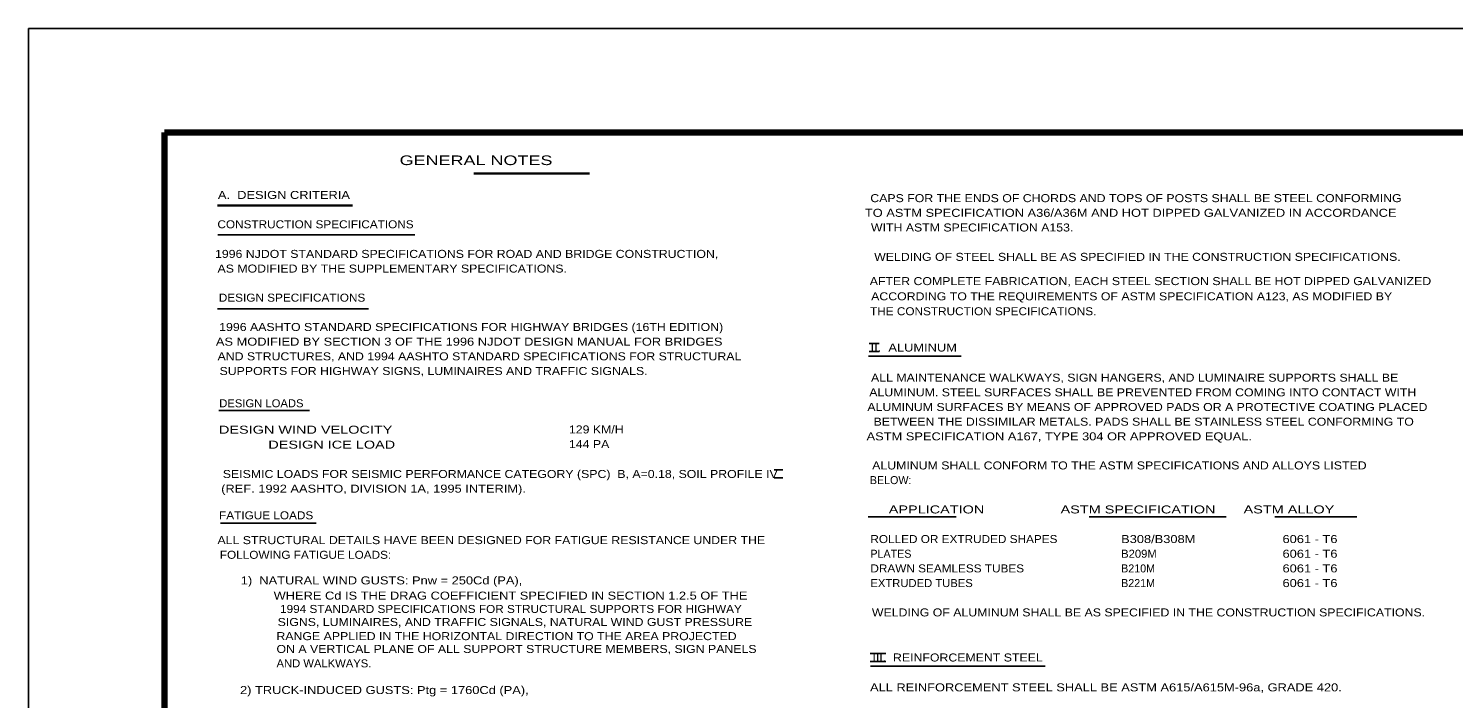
# Model space of a CAD drawing. Extents: x 312601.858 to 312602.699, y 144420.109 to 144420.704.
# Drawn here: x 312601.858 to 312602.392, y 144420.452 to 144420.704 of the extents above; entities that cross this region are included whole.
import ezdxf
from ezdxf.enums import TextEntityAlignment as Align

# ---------------------------------------------------------------- set-up
doc = ezdxf.new("R2010")
doc.units = 0
doc.header["$LTSCALE"] = 0.0012
for name, color, linetype, lineweight in [('1', 7, 'Continuous', 25), ('2', 7, 'Continuous', 25), ('39', 7, 'Continuous', 25)]:
    doc.layers.add(name, color=color, linetype=linetype, lineweight=lineweight)

msp = doc.modelspace()

# ---------------------------------------------------------------- linework, layer by layer
at = {"layer": '1', "lineweight": 35}
for p, q in [((312602.0247, 144420.6492), (312602.0681, 144420.6492)), ((312601.9286, 144420.6371), (312601.9793, 144420.6371))]:
    msp.add_line(p, q, dxfattribs=at)
at = {"layer": '1'}
for p, q in [((312601.9288, 144420.6262), (312602.0026, 144420.6262)), ((312601.9287, 144420.5984), (312601.9853, 144420.5984)), ((312602.173, 144420.5854), (312602.1767, 144420.5854)), ((312602.1727, 144420.5807), (312602.2074, 144420.5807)), ((312602.173, 144420.5824), (312602.1767, 144420.5824)), ((312601.9291, 144420.5603), (312601.9631, 144420.5603)), ((312602.1373, 144420.538), (312602.1406, 144420.538)), ((312602.1373, 144420.535), (312602.1406, 144420.535)), ((312602.1726, 144420.5204), (312602.2056, 144420.5204)), ((312602.2554, 144420.5204), (312602.3068, 144420.5204)), ((312602.325, 144420.5204), (312602.3557, 144420.5204)), ((312602.1733, 144420.4692), (312602.1792, 144420.4692)), ((312602.1733, 144420.4662), (312602.1792, 144420.4662)), ((312602.1734, 144420.4645), (312602.2389, 144420.4645))]:
    msp.add_line(p, q, dxfattribs=at)
at = {"layer": '2'}
msp.add_line((312601.9298, 144420.5181), (312601.9657, 144420.5181), dxfattribs=at)
at = {"layer": '39'}
for p, q in [((312601.8578, 144420.1095), (312601.8578, 144420.7035)), ((312601.8578, 144420.7035), (312602.6988, 144420.7035))]:
    msp.add_line(p, q, dxfattribs=at)
at = {"layer": '39', "lineweight": 158}
for p, q in [((312601.9088, 144420.1247), (312601.9088, 144420.6645)), ((312601.9088, 144420.6645), (312602.6838, 144420.6645))]:
    msp.add_line(p, q, dxfattribs=at)

# ---------------------------------------------------------------- texts
at = {"layer": '1'}
for s, width, p in [('129 KM/H', 1.15, (312602.0604, 144420.5517)), ('144 PA', 1.15, (312602.0604, 144420.5462)), ('ROLLED OR EXTRUDED SHAPES', 1.1, (312602.1734, 144420.5106)), ('B308/B308M', 1.2, (312602.2674, 144420.5106)), ('6061 - T6', 1.2, (312602.3279, 144420.5106)), ('B209M', 1.05, (312602.2674, 144420.5051)), ('6061 - T6', 1.2, (312602.3279, 144420.5051)), ('DRAWN SEAMLESS TUBES', 1.1, (312602.1734, 144420.4996)), ('6061 - T6', 1.2, (312602.3279, 144420.4996)), ('EXTRUDED TUBES', 1.05, (312602.1734, 144420.4941)), ('6061 - T6', 1.2, (312602.3279, 144420.4941))]:
    msp.add_text(s, height=0.003, dxfattribs=dict(at, width=width)).set_placement(p)
for s, p in [('PLATES', (312602.1734, 144420.5051)), ('B210M', (312602.2674, 144420.4996)), ('B221M', (312602.2674, 144420.4941))]:
    msp.add_text(s, height=0.003, dxfattribs=at).set_placement(p)
at = {"layer": '2'}
for s, height, width, p in [('                         GENERAL NOTES', 0.0036, 1.4, (312602.00215, 144420.6523)), ('A.  DESIGN CRITERIA', 0.003, 1.2, (312601.95355, 144420.6396)), ('CAPS FOR THE ENDS OF CHORDS AND TOPS OF POSTS SHALL BE STEEL CONFORMING ', 0.003, 1.15, (312602.2736, 144420.6384)), ('TO ASTM SPECIFICATION A36/A36M AND HOT DIPPED GALVANIZED IN ACCORDANCE ', 0.003, 1.2, (312602.27165, 144420.6329)), ('CONSTRUCTION SPECIFICATIONS', 0.003, 1.1, (312601.9654, 144420.6286)), ('WITH ASTM SPECIFICATION A153.', 0.003, 1.15, (312602.21155, 144420.6274)), ('1996 NJDOT STANDARD SPECIFICATIONS FOR ROAD AND BRIDGE CONSTRUCTION,', 0.003, 1.15, (312602.02205, 144420.6175)), ('WELDING OF STEEL SHALL BE AS SPECIFIED IN THE CONSTRUCTION SPECIFICATIONS. ', 0.003, 1.15, (312602.27415, 144420.6164)), ('AS MODIFIED BY THE SUPPLEMENTARY SPECIFICATIONS.', 0.003, 1.15, (312601.99415, 144420.612)), ('AFTER COMPLETE FABRICATION, EACH STEEL SECTION SHALL BE HOT DIPPED GALVANIZED', 0.003, 1.15, (312602.2784, 144420.6073)), ('DESIGN SPECIFICATIONS', 0.003, 1.1, (312601.9566, 144420.6011)), ('ACCORDING TO THE REQUIREMENTS OF ASTM SPECIFICATION A123, AS MODIFIED BY', 0.003, 1.15, (312602.27135, 144420.6016)), ('THE CONSTRUCTION SPECIFICATIONS.', 0.003, 1.1, (312602.2157, 144420.596)), ('1996 AASHTO STANDARD SPECIFICATIONS FOR HIGHWAY BRIDGES (16TH EDITION)', 0.003, 1.15, (312602.02375, 144420.5901)), ('AS MODIFIED BY SECTION 3 OF THE 1996 NJDOT DESIGN MANUAL FOR BRIDGES', 0.003, 1.2, (312602.023, 144420.5846)), ('II.  ALUMINUM', 0.003, 1.2, (312602.18965, 144420.5824)), ('AND STRUCTURES, AND 1994 AASHTO STANDARD SPECIFICATIONS FOR STRUCTURAL', 0.003, 1.15, (312602.02685, 144420.5791)), ('SUPPORTS FOR HIGHWAY SIGNS, LUMINAIRES AND TRAFFIC SIGNALS.', 0.003, 1.15, (312602.00965, 144420.5736)), ('ALL MAINTENANCE WALKWAYS, SIGN HANGERS, AND LUMINAIRE SUPPORTS SHALL BE  ', 0.003, 1.15, (312602.27375, 144420.5711)), ('ALUMINUM. STEEL SURFACES SHALL BE PREVENTED FROM COMING INTO CONTACT WITH ', 0.003, 1.15, (312602.27615, 144420.5656)), ('DESIGN LOADS', 0.003, 1.05, (312601.9451, 144420.5615)), ('ALUMINUM SURFACES BY MEANS OF APPROVED PADS OR A PROTECTIVE COATING PLACED', 0.003, 1.15, (312602.27725, 144420.5601)), ('BETWEEN THE DISSIMILAR METALS. PADS SHALL BE STAINLESS STEEL CONFORMING TO ', 0.003, 1.15, (312602.2765, 144420.5546)), ('ASTM SPECIFICATION A167, TYPE 304 OR APPROVED EQUAL.', 0.003, 1.2, (312602.2442, 144420.5491)), ('DESIGN ICE LOAD                                  ', 0.003, 1.35, (312601.99705, 144420.546)), ('ALUMINUM SHALL CONFORM TO THE ASTM SPECIFICATIONS AND ALLOYS LISTED', 0.003, 1.15, (312602.26675, 144420.5382)), ('SEISMIC LOADS FOR SEISMIC PERFORMANCE CATEGORY (SPC)  B, A=0.18, SOIL PROFILE IV', 0.003, 1.15, (312602.03465, 144420.535)), ('(REF. 1992 AASHTO, DIVISION 1A, 1995 INTERIM).', 0.003, 1.2, (312601.98715, 144420.5295)), ('FATIGUE LOADS', 0.003, 1.1, (312601.9469, 144420.5195)), ('APPLICATION                   ASTM SPECIFICATION       ASTM ALLOY', 0.003, 1.35, (312602.2638, 144420.5217)), ('APPLICATION                   ASTM SPECIFICATION       ASTM ALLOY', 0.003, 1.35, (312602.2638, 144420.5217)), ('ALL STRUCTURAL DETAILS HAVE BEEN DESIGNED FOR FATIGUE RESISTANCE UNDER THE', 0.003, 1.15, (312602.0313, 144420.5102)), ('FOLLOWING FATIGUE LOADS:', 0.003, 1.1, (312601.96165, 144420.5047)), ('1)  NATURAL WIND GUSTS: Pnw = 250Cd (PA),', 0.003, 1.2, (312601.99015, 144420.4951)), ('WHERE Cd IS THE DRAG COEFFICIENT SPECIFIED IN SECTION 1.2.5 OF THE', 0.003, 1.2, (312602.0385, 144420.4894)), ('1994 STANDARD SPECIFICATIONS FOR STRUCTURAL SUPPORTS FOR HIGHWAY', 0.003, 1.1, (312602.03865, 144420.4844)), ('SIGNS, LUMINAIRES, AND TRAFFIC SIGNALS, NATURAL WIND GUST PRESSURE', 0.003, 1.15, (312602.04015, 144420.4795)), ('WELDING OF ALUMINUM SHALL BE AS SPECIFIED IN THE CONSTRUCTION SPECIFICATIONS.', 0.003, 1.15, (312602.27765, 144420.4831)), ('RANGE APPLIED IN THE HORIZONTAL DIRECTION TO THE AREA PROJECTED', 0.003, 1.15, (312602.037, 144420.4742)), ('ON A VERTICAL PLANE OF ALL SUPPORT STRUCTURE MEMBERS, SIGN PANELS', 0.003, 1.15, (312602.04075, 144420.4694)), ('AND WALKWAYS.', 0.003, 1.05, (312601.96855, 144420.464)), ('III.  REINFORCEMENT STEEL', 0.003, 1.15, (312602.2061, 144420.4662)), ('2) TRUCK-INDUCED GUSTS: Ptg = 1760Cd (PA),', 0.003, 1.2, (312601.9912, 144420.454)), ('ALL REINFORCEMENT STEEL SHALL BE ASTM A615/A615M-96a, GRADE 420.', 0.003, 1.2, (312602.2617, 144420.455))]:
    msp.add_text(s, height=height, dxfattribs=dict(at, width=width)).set_placement(p, align=Align.CENTER)
at = {"layer": '2', "width": 1.35}
msp.add_text('DESIGN WIND VELOCITY                              ', height=0.003, dxfattribs=at).set_placement((312601.9292, 144420.5516))
at = {"layer": '2'}
msp.add_text('BELOW:', height=0.003, dxfattribs=at).set_placement((312602.181, 144420.5327), align=Align.CENTER)

doc.saveas('drawing.dxf')
